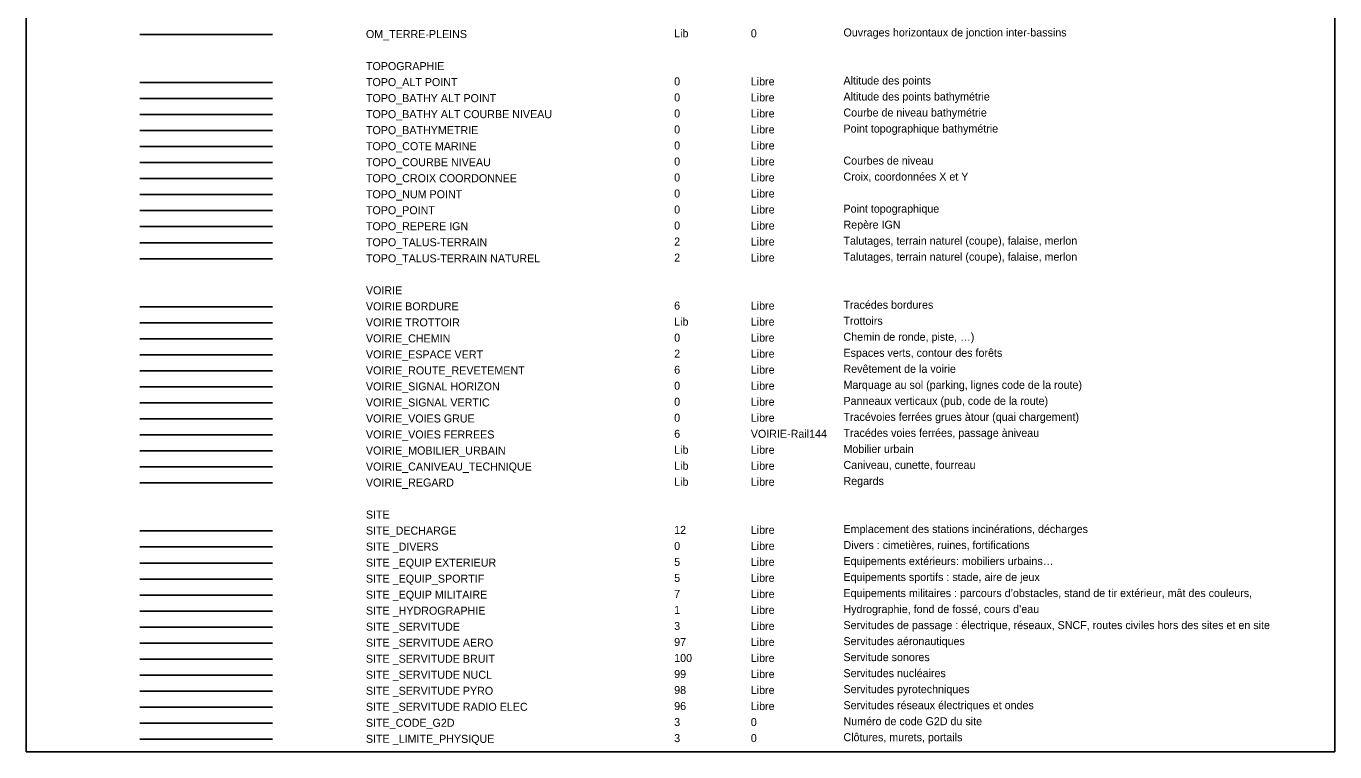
# Model space of a CAD drawing. Extents: x -60 to 214, y -380 to -21.
# Drawn here: x 33.1 to 114.8, y -380.2 to -334.9 of the extents above; entities that cross this region are included whole.
import ezdxf

# ---------------------------------------------------------------- set-up
doc = ezdxf.new("R2010")
doc.units = 0
for name, color, linetype in [('Default', 7, 'Continuous'), ('DH_TEXTE', 7, 'Continuous'), ('OM_TERRE-PLEINS', 7, 'Continuous'), ('SITE _DIVERS', 7, 'Continuous'), ('SITE _EQUIP EXTERIEUR', 7, 'Continuous'), ('SITE _EQUIP MILITAIRE', 7, 'Continuous'), ('SITE _EQUIP_SPORTIF', 7, 'Continuous'), ('SITE _HYDROGRAPHIE', 7, 'Continuous'), ('SITE _LIMITE_PHYSIQUE', 7, 'Continuous'), ('SITE _SERVITUDE', 7, 'Continuous'), ('SITE _SERVITUDE AERO', 7, 'Continuous'), ('SITE _SERVITUDE BRUIT', 7, 'Continuous'), ('SITE _SERVITUDE NUCL', 7, 'Continuous'), ('SITE _SERVITUDE PYRO', 7, 'Continuous'), ('SITE _SERVITUDE RADIO ELEC', 7, 'Continuous'), ('SITE_CODE_G2D', 7, 'Continuous'), ('SITE_DECHARGE', 7, 'Continuous'), ('TOPO_ALT POINT', 7, 'Continuous'), ('TOPO_BATHY ALT COURBE NIVEAU', 7, 'Continuous'), ('TOPO_BATHY ALT POINT', 7, 'Continuous'), ('TOPO_BATHYMETRIE', 7, 'Continuous'), ('TOPO_COTE MARINE', 7, 'Continuous'), ('TOPO_COURBE NIVEAU', 7, 'Continuous'), ('TOPO_CROIX COORDONNEE', 7, 'Continuous'), ('TOPO_NUM POINT', 7, 'Continuous'), ('TOPO_POINT', 7, 'Continuous'), ('TOPO_REPERE IGN', 7, 'Continuous'), ('TOPO_TALUS-TERRAIN', 7, 'Continuous'), ('TOPO_TALUS-TERRAIN NATUREL', 7, 'Continuous'), ('VOIRIE BORDURE', 7, 'Continuous'), ('VOIRIE TROTTOIR', 7, 'Continuous'), ('VOIRIE_CANIVEAU_TECHNIQUE', 7, 'Continuous'), ('VOIRIE_CHEMIN', 7, 'Continuous'), ('VOIRIE_ESPACE VERT', 7, 'Continuous'), ('VOIRIE_MOBILIER_URBAIN', 7, 'Continuous'), ('VOIRIE_REGARD', 7, 'Continuous'), ('VOIRIE_ROUTE_REVETEMENT', 7, 'Continuous'), ('VOIRIE_SIGNAL HORIZON', 7, 'Continuous'), ('VOIRIE_SIGNAL VERTIC', 7, 'Continuous'), ('VOIRIE_VOIES FERREES', 7, 'Continuous'), ('VOIRIE_VOIES GRUE', 7, 'Continuous')]:
    doc.layers.add(name, color=color, linetype=linetype)

msp = doc.modelspace()

# ---------------------------------------------------------------- linework, layer by layer
at = {"layer": 'Default'}
msp.add_lwpolyline([(114.838, -25.727), (33.073, -25.727), (33.073, -380.216), (114.838, -380.216)], close=True, dxfattribs=at)
at = {"layer": 'OM_TERRE-PLEINS'}
msp.add_line((40.178, -335.429), (48.457, -335.429), dxfattribs=at)
at = {"layer": 'SITE _DIVERS'}
msp.add_line((40.178, -367.429), (48.457, -367.429), dxfattribs=at)
at = {"layer": 'SITE _EQUIP EXTERIEUR'}
msp.add_line((40.178, -368.429), (48.457, -368.429), dxfattribs=at)
at = {"layer": 'SITE _EQUIP MILITAIRE'}
msp.add_line((40.178, -370.429), (48.457, -370.429), dxfattribs=at)
at = {"layer": 'SITE _EQUIP_SPORTIF'}
msp.add_line((40.178, -369.429), (48.457, -369.429), dxfattribs=at)
at = {"layer": 'SITE _HYDROGRAPHIE'}
msp.add_line((40.178, -371.429), (48.457, -371.429), dxfattribs=at)
at = {"layer": 'SITE _LIMITE_PHYSIQUE'}
msp.add_line((40.178, -379.429), (48.457, -379.429), dxfattribs=at)
at = {"layer": 'SITE _SERVITUDE'}
msp.add_line((40.178, -372.429), (48.457, -372.429), dxfattribs=at)
at = {"layer": 'SITE _SERVITUDE AERO'}
msp.add_line((40.178, -373.429), (48.457, -373.429), dxfattribs=at)
at = {"layer": 'SITE _SERVITUDE BRUIT'}
msp.add_line((40.178, -374.429), (48.457, -374.429), dxfattribs=at)
at = {"layer": 'SITE _SERVITUDE NUCL'}
msp.add_line((40.178, -375.429), (48.457, -375.429), dxfattribs=at)
at = {"layer": 'SITE _SERVITUDE PYRO'}
msp.add_line((40.178, -376.429), (48.457, -376.429), dxfattribs=at)
at = {"layer": 'SITE _SERVITUDE RADIO ELEC'}
msp.add_line((40.178, -377.429), (48.457, -377.429), dxfattribs=at)
at = {"layer": 'SITE_CODE_G2D'}
msp.add_line((40.178, -378.429), (48.457, -378.429), dxfattribs=at)
at = {"layer": 'SITE_DECHARGE'}
msp.add_line((40.178, -366.429), (48.457, -366.429), dxfattribs=at)
at = {"layer": 'TOPO_ALT POINT'}
msp.add_line((40.178, -338.429), (48.457, -338.429), dxfattribs=at)
at = {"layer": 'TOPO_BATHY ALT COURBE NIVEAU'}
msp.add_line((40.178, -340.429), (48.457, -340.429), dxfattribs=at)
at = {"layer": 'TOPO_BATHY ALT POINT'}
msp.add_line((40.178, -339.429), (48.457, -339.429), dxfattribs=at)
at = {"layer": 'TOPO_BATHYMETRIE'}
msp.add_line((40.178, -341.429), (48.457, -341.429), dxfattribs=at)
at = {"layer": 'TOPO_COTE MARINE'}
msp.add_line((40.178, -342.429), (48.457, -342.429), dxfattribs=at)
at = {"layer": 'TOPO_COURBE NIVEAU'}
msp.add_line((40.178, -343.429), (48.457, -343.429), dxfattribs=at)
at = {"layer": 'TOPO_CROIX COORDONNEE'}
msp.add_line((40.178, -344.429), (48.457, -344.429), dxfattribs=at)
at = {"layer": 'TOPO_NUM POINT'}
msp.add_line((40.178, -345.429), (48.457, -345.429), dxfattribs=at)
at = {"layer": 'TOPO_POINT'}
msp.add_line((40.178, -346.429), (48.457, -346.429), dxfattribs=at)
at = {"layer": 'TOPO_REPERE IGN'}
msp.add_line((40.178, -347.429), (48.457, -347.429), dxfattribs=at)
at = {"layer": 'TOPO_TALUS-TERRAIN'}
msp.add_line((40.178, -348.429), (48.457, -348.429), dxfattribs=at)
at = {"layer": 'TOPO_TALUS-TERRAIN NATUREL'}
msp.add_line((40.178, -349.429), (48.457, -349.429), dxfattribs=at)
at = {"layer": 'VOIRIE BORDURE'}
msp.add_line((40.178, -352.429), (48.457, -352.429), dxfattribs=at)
at = {"layer": 'VOIRIE TROTTOIR'}
msp.add_line((40.178, -353.429), (48.457, -353.429), dxfattribs=at)
at = {"layer": 'VOIRIE_CANIVEAU_TECHNIQUE'}
msp.add_line((40.178, -362.429), (48.457, -362.429), dxfattribs=at)
at = {"layer": 'VOIRIE_CHEMIN'}
msp.add_line((40.178, -354.429), (48.457, -354.429), dxfattribs=at)
at = {"layer": 'VOIRIE_ESPACE VERT'}
msp.add_line((40.178, -355.429), (48.457, -355.429), dxfattribs=at)
at = {"layer": 'VOIRIE_MOBILIER_URBAIN'}
msp.add_line((40.178, -361.429), (48.457, -361.429), dxfattribs=at)
at = {"layer": 'VOIRIE_REGARD'}
msp.add_line((40.178, -363.429), (48.457, -363.429), dxfattribs=at)
at = {"layer": 'VOIRIE_ROUTE_REVETEMENT'}
msp.add_line((40.178, -356.429), (48.457, -356.429), dxfattribs=at)
at = {"layer": 'VOIRIE_SIGNAL HORIZON'}
msp.add_line((40.178, -357.429), (48.457, -357.429), dxfattribs=at)
at = {"layer": 'VOIRIE_SIGNAL VERTIC'}
msp.add_line((40.178, -358.429), (48.457, -358.429), dxfattribs=at)
at = {"layer": 'VOIRIE_VOIES FERREES'}
msp.add_line((40.178, -360.429), (48.457, -360.429), dxfattribs=at)
at = {"layer": 'VOIRIE_VOIES GRUE'}
msp.add_line((40.178, -359.429), (48.457, -359.429), dxfattribs=at)

# ---------------------------------------------------------------- texts
at = {"layer": 'DH_TEXTE'}
for s, p in [('TOPOGRAPHIE ', (54.301, -337.655)), ('VOIRIE ', (54.301, -351.655)), ('SITE ', (54.301, -365.655))]:
    msp.add_text(s, height=0.5, dxfattribs=at).set_placement(p)
at = {"layer": 'OM_TERRE-PLEINS'}
for s, p in [('OM_TERRE-PLEINS ', (54.301, -335.655)), ('Lib ', (73.561, -335.61)), ('0', (78.348, -335.61)), ('Ouvrages horizontaux de jonction inter-bassins ', (84.14, -335.555))]:
    msp.add_text(s, height=0.5, dxfattribs=at).set_placement(p)
at = {"layer": 'SITE _DIVERS'}
for s, p in [('0 ', (73.561, -367.61)), ('Libre', (78.348, -367.61)), ('Divers : cimetières, ruines, fortifications  ', (84.138, -367.555)), ('SITE _DIVERS ', (54.301, -367.655))]:
    msp.add_text(s, height=0.5, dxfattribs=at).set_placement(p)
at = {"layer": 'SITE _EQUIP EXTERIEUR'}
for s, p in [('SITE _EQUIP EXTERIEUR  ', (54.301, -368.655)), ('5 ', (73.561, -368.61)), ('Libre', (78.348, -368.61)), ('Equipements extérieurs: mobiliers urbains… ', (84.138, -368.555))]:
    msp.add_text(s, height=0.5, dxfattribs=at).set_placement(p)
at = {"layer": 'SITE _EQUIP MILITAIRE'}
for s, p in [('SITE _EQUIP MILITAIRE ', (54.301, -370.655)), ('7 ', (73.561, -370.61)), ('Libre', (78.348, -370.61)), ('Equipements militaires : parcours d’obstacles, stand de tir extérieur, mât des couleurs,  ', (84.138, -370.555))]:
    msp.add_text(s, height=0.5, dxfattribs=at).set_placement(p)
at = {"layer": 'SITE _EQUIP_SPORTIF'}
for s, p in [('SITE _EQUIP_SPORTIF ', (54.301, -369.655)), ('5 ', (73.561, -369.61)), ('Libre', (78.348, -369.61)), ('Equipements sportifs : stade, aire de jeux ', (84.138, -369.555))]:
    msp.add_text(s, height=0.5, dxfattribs=at).set_placement(p)
at = {"layer": 'SITE _HYDROGRAPHIE'}
for s, p in [('SITE _HYDROGRAPHIE  ', (54.301, -371.655)), ('1 ', (73.561, -371.61)), ('Libre', (78.348, -371.61)), ('Hydrographie, fond de fossé, cours d’eau ', (84.138, -371.555))]:
    msp.add_text(s, height=0.5, dxfattribs=at).set_placement(p)
at = {"layer": 'SITE _LIMITE_PHYSIQUE'}
for s, p in [('SITE _LIMITE_PHYSIQUE ', (54.301, -379.655)), ('3 ', (73.561, -379.61)), ('0', (78.348, -379.61)), ('Clôtures, murets, portails ', (84.138, -379.555))]:
    msp.add_text(s, height=0.5, dxfattribs=at).set_placement(p)
at = {"layer": 'SITE _SERVITUDE'}
for s, p in [('Servitudes de passage : électrique, réseaux, SNCF, routes civiles hors des sites et en site ', (84.138, -372.555)), ('SITE _SERVITUDE  ', (54.301, -372.655)), ('3 ', (73.561, -372.61)), ('Libre', (78.348, -372.61))]:
    msp.add_text(s, height=0.5, dxfattribs=at).set_placement(p)
at = {"layer": 'SITE _SERVITUDE AERO'}
for s, p in [('SITE _SERVITUDE AERO ', (54.301, -373.655)), ('97 ', (73.561, -373.61)), ('Libre', (78.348, -373.61)), ('Servitudes aéronautiques ', (84.138, -373.555))]:
    msp.add_text(s, height=0.5, dxfattribs=at).set_placement(p)
at = {"layer": 'SITE _SERVITUDE BRUIT'}
for s, p in [('SITE _SERVITUDE BRUIT ', (54.301, -374.655)), ('100 ', (73.561, -374.61)), ('Libre', (78.348, -374.61)), ('Servitude sonores ', (84.138, -374.555))]:
    msp.add_text(s, height=0.5, dxfattribs=at).set_placement(p)
at = {"layer": 'SITE _SERVITUDE NUCL'}
for s, p in [('SITE _SERVITUDE NUCL ', (54.301, -375.655)), ('99 ', (73.561, -375.61)), ('Libre', (78.348, -375.61)), ('Servitudes nucléaires ', (84.138, -375.555))]:
    msp.add_text(s, height=0.5, dxfattribs=at).set_placement(p)
at = {"layer": 'SITE _SERVITUDE PYRO'}
for s, p in [('98 ', (73.561, -376.61)), ('Libre', (78.348, -376.61)), ('Servitudes pyrotechniques ', (84.138, -376.555)), ('SITE _SERVITUDE PYRO ', (54.301, -376.655))]:
    msp.add_text(s, height=0.5, dxfattribs=at).set_placement(p)
at = {"layer": 'SITE _SERVITUDE RADIO ELEC'}
for s, p in [('SITE _SERVITUDE RADIO ELEC ', (54.301, -377.655)), ('96 ', (73.561, -377.61)), ('Libre', (78.348, -377.61)), ('Servitudes réseaux électriques et ondes ', (84.138, -377.555))]:
    msp.add_text(s, height=0.5, dxfattribs=at).set_placement(p)
at = {"layer": 'SITE_CODE_G2D'}
for s, p in [('SITE_CODE_G2D ', (54.301, -378.655)), ('3 ', (73.561, -378.61)), ('0', (78.348, -378.61)), ('Numéro de code G2D du site ', (84.138, -378.555))]:
    msp.add_text(s, height=0.5, dxfattribs=at).set_placement(p)
at = {"layer": 'SITE_DECHARGE'}
for s, p in [('SITE_DECHARGE ', (54.301, -366.655)), ('12 ', (73.559, -366.61)), ('Libre', (78.348, -366.61)), ('Emplacement des stations incinérations, décharges  ', (84.138, -366.555))]:
    msp.add_text(s, height=0.5, dxfattribs=at).set_placement(p)
at = {"layer": 'TOPO_ALT POINT'}
for s, p in [('TOPO_ALT POINT  ', (54.301, -338.655)), ('0', (73.559, -338.61)), ('Libre', (78.348, -338.61)), ('Altitude des points ', (84.138, -338.555))]:
    msp.add_text(s, height=0.5, dxfattribs=at).set_placement(p)
at = {"layer": 'TOPO_BATHY ALT COURBE NIVEAU'}
for s, p in [('0', (73.559, -340.61)), ('Libre', (78.348, -340.61)), ('Courbe de niveau bathymétrie ', (84.138, -340.555)), ('TOPO_BATHY ALT COURBE NIVEAU  ', (54.301, -340.655))]:
    msp.add_text(s, height=0.5, dxfattribs=at).set_placement(p)
at = {"layer": 'TOPO_BATHY ALT POINT'}
for s, p in [('TOPO_BATHY ALT POINT', (54.301, -339.655)), ('0', (73.559, -339.61)), ('Libre', (78.348, -339.61)), ('Altitude des points bathymétrie ', (84.138, -339.555))]:
    msp.add_text(s, height=0.5, dxfattribs=at).set_placement(p)
at = {"layer": 'TOPO_BATHYMETRIE'}
for s, p in [('TOPO_BATHYMETRIE ', (54.301, -341.655)), ('0', (73.559, -341.61)), ('Libre', (78.348, -341.61)), ('Point topographique bathymétrie  ', (84.138, -341.555))]:
    msp.add_text(s, height=0.5, dxfattribs=at).set_placement(p)
at = {"layer": 'TOPO_COTE MARINE'}
for s, p in [('TOPO_COTE MARINE ', (54.301, -342.655)), ('0', (73.561, -342.61)), ('Libre', (78.348, -342.61))]:
    msp.add_text(s, height=0.5, dxfattribs=at).set_placement(p)
at = {"layer": 'TOPO_COURBE NIVEAU'}
for s, p in [('TOPO_COURBE NIVEAU  ', (54.301, -343.655)), ('0', (73.561, -343.61)), ('Libre', (78.348, -343.61)), ('Courbes de niveau ', (84.138, -343.555))]:
    msp.add_text(s, height=0.5, dxfattribs=at).set_placement(p)
at = {"layer": 'TOPO_CROIX COORDONNEE'}
for s, p in [('TOPO_CROIX COORDONNEE  ', (54.301, -344.655)), ('0', (73.561, -344.61)), ('Libre', (78.348, -344.61)), ('Croix, coordonnées X et Y  ', (84.138, -344.555))]:
    msp.add_text(s, height=0.5, dxfattribs=at).set_placement(p)
at = {"layer": 'TOPO_NUM POINT'}
for s, p in [('TOPO_NUM POINT ', (54.301, -345.655)), ('0', (73.561, -345.61)), ('Libre', (78.348, -345.61))]:
    msp.add_text(s, height=0.5, dxfattribs=at).set_placement(p)
at = {"layer": 'TOPO_POINT'}
for s, p in [('TOPO_POINT  ', (54.301, -346.655)), ('0', (73.561, -346.61)), ('Libre', (78.348, -346.61)), ('Point topographique ', (84.138, -346.555))]:
    msp.add_text(s, height=0.5, dxfattribs=at).set_placement(p)
at = {"layer": 'TOPO_REPERE IGN'}
for s, p in [('TOPO_REPERE IGN ', (54.301, -347.655)), ('0', (73.559, -347.61)), ('Libre', (78.348, -347.61)), ('Repère IGN ', (84.138, -347.555))]:
    msp.add_text(s, height=0.5, dxfattribs=at).set_placement(p)
at = {"layer": 'TOPO_TALUS-TERRAIN'}
for s, p in [('TOPO_TALUS-TERRAIN ', (54.301, -348.655)), ('2', (73.561, -348.61)), ('Libre', (78.348, -348.61)), ('Talutages, terrain naturel (coupe), falaise, merlon ', (84.138, -348.555))]:
    msp.add_text(s, height=0.5, dxfattribs=at).set_placement(p)
at = {"layer": 'TOPO_TALUS-TERRAIN NATUREL'}
for s, p in [('2', (73.561, -349.61)), ('Libre', (78.348, -349.61)), ('Talutages, terrain naturel (coupe), falaise, merlon ', (84.138, -349.555)), ('TOPO_TALUS-TERRAIN NATUREL', (54.301, -349.655))]:
    msp.add_text(s, height=0.5, dxfattribs=at).set_placement(p)
at = {"layer": 'VOIRIE BORDURE'}
for s, p in [('VOIRIE BORDURE  ', (54.301, -352.655)), ('6 ', (73.559, -352.61)), ('Libre', (78.348, -352.61)), ('Tracédes bordures  ', (84.138, -352.555))]:
    msp.add_text(s, height=0.5, dxfattribs=at).set_placement(p)
at = {"layer": 'VOIRIE TROTTOIR'}
for s, p in [('VOIRIE TROTTOIR ', (54.301, -353.655)), ('Lib ', (73.561, -353.61)), ('Libre', (78.348, -353.61)), ('Trottoirs ', (84.138, -353.555))]:
    msp.add_text(s, height=0.5, dxfattribs=at).set_placement(p)
at = {"layer": 'VOIRIE_CANIVEAU_TECHNIQUE'}
for s, p in [('VOIRIE_CANIVEAU_TECHNIQUE ', (54.301, -362.655)), ('Lib ', (73.561, -362.61)), ('Libre', (78.348, -362.61)), ('Caniveau, cunette, fourreau ', (84.138, -362.555))]:
    msp.add_text(s, height=0.5, dxfattribs=at).set_placement(p)
at = {"layer": 'VOIRIE_CHEMIN'}
for s, p in [('Chemin de ronde, piste, …) ', (84.138, -354.555)), ('VOIRIE_CHEMIN ', (54.301, -354.655)), ('0 ', (73.561, -354.61)), ('Libre', (78.348, -354.61))]:
    msp.add_text(s, height=0.5, dxfattribs=at).set_placement(p)
at = {"layer": 'VOIRIE_ESPACE VERT'}
for s, p in [('VOIRIE_ESPACE VERT  ', (54.301, -355.655)), ('2 ', (73.561, -355.61)), ('Libre', (78.348, -355.61)), ('Espaces verts, contour des forêts ', (84.138, -355.555))]:
    msp.add_text(s, height=0.5, dxfattribs=at).set_placement(p)
at = {"layer": 'VOIRIE_MOBILIER_URBAIN'}
for s, p in [('VOIRIE_MOBILIER_URBAIN ', (54.301, -361.655)), ('Lib ', (73.561, -361.61)), ('Libre', (78.348, -361.61)), ('Mobilier urbain ', (84.138, -361.555))]:
    msp.add_text(s, height=0.5, dxfattribs=at).set_placement(p)
at = {"layer": 'VOIRIE_REGARD'}
for s, p in [('Regards ', (84.138, -363.555)), ('VOIRIE_REGARD ', (54.301, -363.655)), ('Lib ', (73.561, -363.61)), ('Libre', (78.348, -363.61))]:
    msp.add_text(s, height=0.5, dxfattribs=at).set_placement(p)
at = {"layer": 'VOIRIE_ROUTE_REVETEMENT'}
for s, p in [('VOIRIE_ROUTE_REVETEMENT ', (54.301, -356.655)), ('6 ', (73.561, -356.61)), ('Libre', (78.348, -356.61)), ('Revêtement de la voirie ', (84.138, -356.555))]:
    msp.add_text(s, height=0.5, dxfattribs=at).set_placement(p)
at = {"layer": 'VOIRIE_SIGNAL HORIZON'}
for s, p in [('VOIRIE_SIGNAL HORIZON ', (54.301, -357.655)), ('0 ', (73.561, -357.61)), ('Libre', (78.348, -357.61)), ('Marquage au sol (parking, lignes code de la route) ', (84.138, -357.555))]:
    msp.add_text(s, height=0.5, dxfattribs=at).set_placement(p)
at = {"layer": 'VOIRIE_SIGNAL VERTIC'}
for s, p in [('0 ', (73.561, -358.61)), ('Libre', (78.348, -358.61)), ('Panneaux verticaux (pub, code de la route) ', (84.138, -358.555)), ('VOIRIE_SIGNAL VERTIC ', (54.301, -358.655))]:
    msp.add_text(s, height=0.5, dxfattribs=at).set_placement(p)
at = {"layer": 'VOIRIE_VOIES FERREES'}
for s, p in [('VOIRIE_VOIES FERREES ', (54.301, -360.655)), ('6 ', (73.561, -360.61)), ('VOIRIE-Rail144', (78.348, -360.61)), ('Tracédes voies ferrées, passage àniveau ', (84.138, -360.555))]:
    msp.add_text(s, height=0.5, dxfattribs=at).set_placement(p)
at = {"layer": 'VOIRIE_VOIES GRUE'}
for s, p in [('VOIRIE_VOIES GRUE ', (54.301, -359.655)), ('0 ', (73.561, -359.61)), ('Libre', (78.348, -359.61)), ('Tracévoies ferrées grues àtour (quai chargement) ', (84.138, -359.555))]:
    msp.add_text(s, height=0.5, dxfattribs=at).set_placement(p)

doc.saveas('drawing.dxf')
